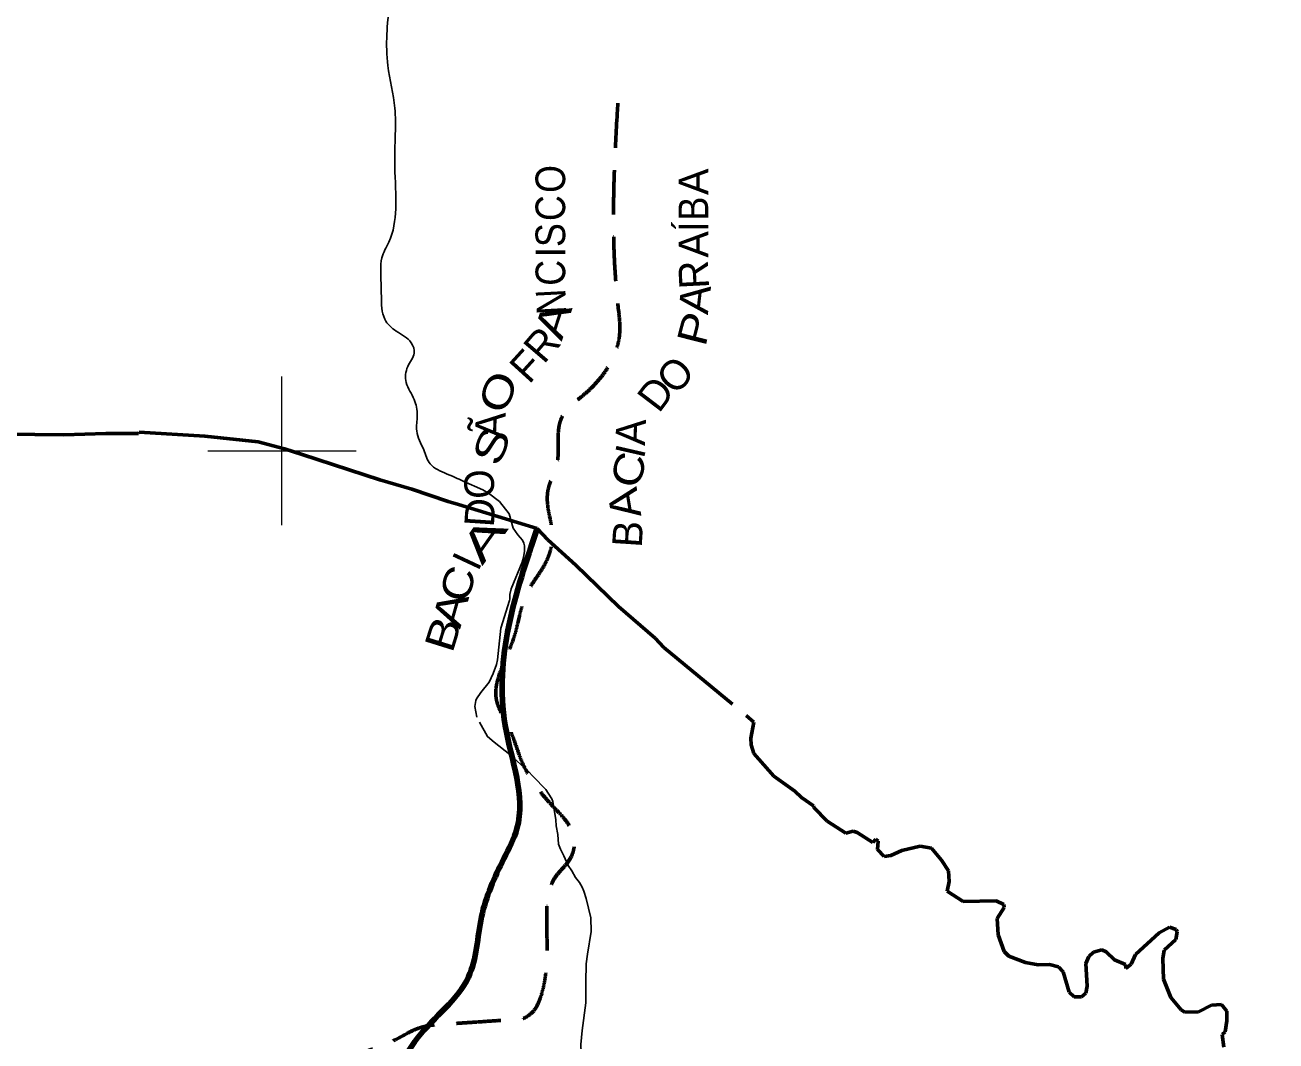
# Model space of a CAD drawing. Extents: x 553962 to 842807, y 8883888 to 9032388.
# Drawn here: x 746538 to 763398, y 8967044 to 8980740 of the extents above; entities that cross this region are included whole.
import ezdxf
from ezdxf.enums import TextEntityAlignment as Align

# ---------------------------------------------------------------- set-up
doc = ezdxf.new("R2010")
doc.units = 0
doc.header["$LTSCALE"] = 200
doc.linetypes.add('LONG_DASH_SHORT_DASH', pattern=[9.9, 6, -1.2, 1.5, -1.2])
doc.linetypes.add('MEDIUM_DASHED', pattern=[4.5, 3, -1.5])
for name, color, linetype, lineweight in [('10', 7, 'MEDIUM_DASHED', 60), ('12', 7, 'Continuous', 25), ('2', 7, 'Continuous', 13), ('24', 7, 'Continuous', 25), ('7', 7, 'LONG_DASH_SHORT_DASH', 60), ('9', 7, 'Continuous', 90)]:
    doc.layers.add(name, color=color, linetype=linetype, lineweight=lineweight)

msp = doc.modelspace()

# ---------------------------------------------------------------- linework, layer by layer
at = {"layer": '10'}
msp.add_spline([(753353.8, 8967411.3), (753402.1, 8967459.7), (753447.5, 8967537.9), (753569.9, 8968137.4), (753569.9, 8968618.2), (753685.3, 8969252.9), (753896.8, 8969522.2), (753935.3, 8969791.5), (753646.8, 8970214.6), (753242.9, 8970791.6), (753050.6, 8971291.7), (752896.7, 8971618.7), (753127.5, 8972484.2), (753300.6, 8973080.5), (753550.6, 8973484.4), (753646.8, 8973869.1), (753589.1, 8974215.3), (753589.1, 8974484.5), (753704.5, 8974811.5), (753723.7, 8975177), (753762.2, 8975427), (754089.2, 8975773.2), (754377.7, 8976100.2), (754550.8, 8976561.8), (754531.6, 8976946.5), (754538.8, 8979865.5)], degree=3, dxfattribs=at)
msp.add_open_spline([(751718.9, 8957290.2), (751531.6, 8957712.2), (750995.8, 8957861.4), (750836, 8958259.9), (750739.1, 8958501.4), (750810.6, 8958803), (750701.7, 8959043.4), (750649.5, 8959158.5), (750585.8, 8959273.1), (750522.6, 8959379.2), (750416.4, 8959557.6), (750245.2, 8959714.4), (750142.1, 8959894), (750059.8, 8960037.4), (750424.3, 8960195.8), (750388.3, 8960341.7), (750306, 8960675.5), (749757.2, 8960933.4), (749694.4, 8961281.9), (749657.1, 8961488.8), (749737.2, 8961760.6), (749694.4, 8961975.8), (749670.2, 8962097.1), (749510.2, 8962210.1), (749537.7, 8962334), (749613.3, 8962675.1), (749758.5, 8963019.6), (749851.1, 8963363.7), (749964, 8963783.7), (750022.5, 8964223.4), (750164.5, 8964639.7), (750243.4, 8964871.2), (750497.6, 8964991.5), (750634.5, 8965199.3), (750728.3, 8965341.6), (750833.7, 8965482.3), (750858.4, 8965647), (750892.9, 8965877.2), (750782, 8966109.4), (750768.8, 8966340.9), (750760.8, 8966481.8), (750668.1, 8966638.3), (750791.2, 8966766.2), (750923.4, 8966903.6), (751072.8, 8966882.1), (751216.6, 8966934), (751537.1, 8967049.7), (751840, 8967247.2), (752179.1, 8967269.8), (752291, 8967277.3), (752403, 8967284.8), (752514.9, 8967292.2), (752738.7, 8967307.2), (752962.6, 8967322.1), (753186.4, 8967337), (753247.3, 8967341.1), (753307.9, 8967370.8), (753353.8, 8967411.3)], degree=3, dxfattribs=at)
at = {"layer": '12'}
for points in [[(752444.7, 8974591.9), (752707.4, 8974475.5), (752786.5, 8974428), (752930.8, 8974317.1), (753062.6, 8974152.6), (753117.5, 8973959.1), (753180.2, 8973867.8), (753242.2, 8973795.8), (753262.4, 8973756.4), (753269, 8973717.7), (753270.2, 8973648.7), (753257.3, 8973562.4), (753237.5, 8973498.7), (753090.9, 8973141.2), (753070.7, 8973063.5), (753072.3, 8973000.7), (753069.1, 8972980.9), (752948.8, 8972607.6), (752907.8, 8972182.6), (752892.3, 8972118.5), (752847.2, 8971998.1), (752793, 8971880.4), (752680.5, 8971744), (752622, 8971655), (752613.9, 8971634.4), (752600.5, 8971552.9), (752626, 8971408.9)], [(752664, 8971340.7), (752771, 8971148.4), (752859.2, 8971072.4), (753072.2, 8970907.4), (753319.1, 8970681.2), (753384.5, 8970609.5), (753558.8, 8970434.3), (753589.6, 8970386.1)], [(753589.6, 8970386.1), (753640.4, 8970306.5), (753650.2, 8970274.2), (753691.1, 8970026.8), (753698.8, 8969944.5), (753719.3, 8969828.1), (753728.3, 8969699.4), (753756.5, 8969629.3), (753798.1, 8969540.9)], [(753798.1, 8969540.9), (753859.8, 8969409.4), (753909.1, 8969336.8), (753959.2, 8969249.6), (754012.5, 8969179), (754046.6, 8969117.8), (754069.8, 8969065.7), (754101.8, 8968966.1), (754161.6, 8968706.3), (754168.3, 8968520.8), (754116.9, 8968213), (754102.8, 8968082.3), (754094.2, 8967837.6), (754098.2, 8967608.9), (754095, 8967556.7), (754045.7, 8967185.6), (754028.2, 8966994.8), (754035.8, 8966766.1), (754034.7, 8966701.8), (754052, 8966621.5), (754053.6, 8966322.7), (754067.7, 8966231)]]:
    msp.add_lwpolyline(points, dxfattribs=at)
msp.add_spline([(752444.7, 8974591.9), (752220.7, 8974690.3), (751998.9, 8974824.7), (751911.5, 8975012.9), (751817.4, 8975268.3), (751824.1, 8975476.7), (751783.8, 8975691.7), (751676.2, 8975920.3), (751696.4, 8976135.3), (751783.8, 8976316.8), (751743.5, 8976458), (751541.8, 8976612.5), (751387.2, 8976773.8), (751340.2, 8977083), (751333.5, 8977432.5), (751346.9, 8977600.6), (751441, 8977812.6), (751535.1, 8978263.1), (751521.7, 8978828), (751528.4, 8979271.8), (751521.7, 8979621.5), (751427.6, 8980193.1), (751414.1, 8980616.7), (751461.2, 8981006.8), (751622.5, 8981450.6), (751723.3, 8981645.6), (752140.5, 8982419.4)], degree=3, dxfattribs=at)
at = {"layer": '2'}
for p, q in [((750000, 8974000), (750000, 8976000)), ((749000, 8975000), (751000, 8975000))]:
    msp.add_line(p, q, dxfattribs=at)
at = {"layer": '24'}
msp.add_spline([(771983.6, 8980431.6), (771458.1, 8980369.7), (771148.9, 8980648.1), (771087.1, 8980988.4), (770932.5, 8981297.7), (770808.9, 8981638), (770345.2, 8981761.8), (770005.1, 8981885.5), (769819.6, 8982071.1), (769634.1, 8981854.6), (769479.5, 8982009.2), (769015.8, 8982318.6), (768923.1, 8982689.8), (768706.7, 8982937.2), (768593.5, 8983157.4), (768713.2, 8983415.3), (768842, 8983516.6), (768842, 8983590.2), (768630.3, 8983700.8), (768289.8, 8983940.2), (768207, 8984262.5), (768022.9, 8984465.2), (767700.8, 8984557.2), (767590.3, 8984640.1), (767553.5, 8985036.1), (767599.5, 8985266.4), (767599.5, 8985422.9), (767461.5, 8985607.1), (767314.2, 8985634.8), (767268.2, 8985533.4), (767139.4, 8985496.6), (766918.5, 8985616.3), (766789.6, 8985818.9), (766559.5, 8985957.1), (766219, 8986297.8), (765850.9, 8986500.4), (765363.1, 8986924.1), (764801.7, 8987504.3), (764663.6, 8987624), (764378.3, 8988066), (764295.5, 8988259.4), (764221.8, 8988296.3), (764083.8, 8988204.2), (763982.5, 8988268.6), (763669.6, 8988664.7), (763586.8, 8988683.1), (763540.8, 8988848.8), (763605.2, 8988913.3), (763665, 8988922.5), (763720.2, 8989088.3), (763554.6, 8989254.1), (763480.9, 8989475.1), (763628.2, 8989677.7), (763977.9, 8989935.6), (764143.6, 8990101.3), (764125.2, 8990285.5), (763849.1, 8990377.6), (763793.9, 8990525), (763591.4, 8990617.1), (763480.9, 8990635.5), (763260.1, 8990525), (763094.4, 8990525), (762965.5, 8990635.5), (762818.3, 8990856.5), (762781.5, 8990930.2), (762652.6, 8990967), (762450.1, 8991169.6), (762082, 8991335.4), (761916.3, 8991464.3), (761750.7, 8991464.3), (761640.2, 8991261.7), (761456.2, 8991059.1), (761382.5, 8990967), (761290.5, 8990948.6), (761198.5, 8991059.1), (761143.2, 8991298.6), (760867.1, 8991464.3), (760738.3, 8991666.9), (760499, 8991795.9), (760351.7, 8992035.3), (760094, 8992495.8), (759854.7, 8992403.7), (759652.3, 8992256.3), (759394.6, 8992477.3), (758971.2, 8992643.1), (758731.9, 8992753.6), (758639.9, 8993048.3), (758566.2, 8993324.6), (758695.1, 8993508.8), (758916, 8993453.6), (758879.2, 8993619.3)], degree=3, dxfattribs=at)
at = {"layer": '7'}
msp.add_lwpolyline([(746278.3, 8975226), (747060.9, 8975214.3), (747626.8, 8975234.9), (748067.1, 8975233), (748078.4, 8975249.4), (748961.7, 8975196.1), (749681.4, 8975121.3), (750036, 8975026.7), (750271.4, 8974951.8), (751320.7, 8974608), (751750.1, 8974483.8), (752242.5, 8974318.8), (752380.7, 8974278), (753439.5, 8973954.2), (753583.6, 8973799.8), (753961.2, 8973460.6), (754538, 8972903.3), (755030, 8972474.8), (755147.7, 8972349.6), (756362.8, 8971344), (756320.3, 8971125.1), (756323.8, 8971036.6), (756361.2, 8970920.9), (756631.5, 8970616), (756915, 8970410.1), (757002.6, 8970325.1), (757165.2, 8970215.8), (757167.7, 8970190.1), (757348.9, 8970005.6), (757600.5, 8969846.9), (757701.3, 8969872.7), (757754.8, 8969855.7), (757962.9, 8969718.5), (758005.2, 8969765.2), (758038.1, 8969737.6), (758029.7, 8969624), (758115.6, 8969531.9), (758205.5, 8969542.5), (758357.8, 8969613.2), (758603.6, 8969671), (758755.3, 8969645.6), (758888.7, 8969481.4), (758982.7, 8969336.6), (758994.5, 8969195.7), (758967.2, 8969062.8), (759180.8, 8968923.9), (759628.7, 8968933.4), (759730, 8968884.3), (759736.6, 8968843), (759642.6, 8968697.4), (759656.2, 8968476.3), (759734.5, 8968249.9), (759797.4, 8968186.8), (760020.8, 8968100.7), (760193.3, 8968069.4), (760346.5, 8968073.3), (760468.7, 8968041.8), (760531.4, 8967975.3), (760612.4, 8967703.8), (760676.7, 8967637.3), (760778.2, 8967637.3), (760833.4, 8967688.2), (760853, 8967781.7), (760833.6, 8968087.2), (760876.7, 8968185), (760939.1, 8968243.5), (761053, 8968271), (761107.6, 8968247.7), (761221.6, 8968138.1), (761368.5, 8968077.3), (761376.6, 8968022.9), (761447, 8968077.5), (761506.1, 8968210.7), (761825.6, 8968499.9), (761961, 8968579.3), (762052.9, 8968547.4), (762065.9, 8968514.3), (762049.6, 8968410.7), (761891.1, 8968267.7), (761875.3, 8968158.2), (761883.2, 8967876.5), (761983, 8967632.3), (762120.3, 8967463.7), (762171.6, 8967432.4), (762355.5, 8967436.4), (762528.1, 8967526.2), (762662.3, 8967534.7), (762735.1, 8967446.8), (762735.2, 8967316.2), (762713.7, 8967168.6), (762672.7, 8967130.8), (762696.2, 8966959)], dxfattribs=at)
at = {"layer": '9'}
msp.add_spline([(750521.5, 8957798.6), (750290, 8958657.6), (749980, 8960173.9), (749746.6, 8961538.9), (749919.1, 8962982.1), (750673.6, 8964858.9), (751354.2, 8966153.2), (751832.9, 8967092.2), (752515.2, 8967905.8), (752689.9, 8968716.5), (752991.6, 8969502.6), (753167.8, 8969908.5), (753010.5, 8971299.2), (753439.5, 8973954.2)], degree=3, dxfattribs=at)

# ---------------------------------------------------------------- texts
at = {"layer": '10'}
for s, rotation, width, p in [('O', 90.036, 0.9, (753817.8, 8978665.2)), ('C', 90.036, 0.9, (753818, 8978272.4)), ('B', 90.036, 0.9, (755746.5, 8978265.8)), ('S', 90.036, 0.9, (753818.2, 8977908.6)), ('Í', 90.036, 0.85, (755746.7, 8978022)), ('C', 90.036, 0.9, (753818.6, 8977399.4)), ('A', 83.512, 1.1, (755762.6, 8977022)), ('N', 92.943, 0.9, (753827.9, 8977019.2)), ('A', 72.093, 1.35, (753844.7, 8976698.2)), ('P', 75.752, 1.2, (755758.5, 8976597.7)), ('O', 68.654, 1.3, (753100.6, 8975721.6)), ('S', 68.232, 1.35, (753011.4, 8974993.7)), ('C', 75.108, 1.2, (754866.1, 8974693.7)), ('O', 92.819, 0.95, (752858.4, 8974562.2)), ('A', 99.428, 1.15, (754812.1, 8974324.5)), ('A', 54.756, 1.75, (752879.4, 8973696.6)), ('C', 73.461, 1.2, (752562.8, 8973151.1)), ('A', 74.159, 1.3, (752463.3, 8972809.8)), ('B', 72.657, 1.25, (752362.1, 8972471.4))]:
    msp.add_text(s, height=400, rotation=rotation, dxfattribs=dict(at, width=width)).set_placement(p, align=Align.CENTER)
for s, rotation, p in [('A', 90.036, (755746.3, 8978627.4)), ('A', 90.036, (755746.8, 8977783.2)), ('I', 90.036, (753818.4, 8977676.6)), ('R', 92.943, (755748.6, 8977384.2)), ('R', 49.429, (753655.3, 8976304.3)), ('F', 47.713, (753441.2, 8976008.7)), ('O', 47.713, (755448.4, 8975892)), ('D', 52.701, (755198, 8975649.5)), ('Ã', 87.425, (753008, 8975336.6)), ('A', 87.425, (754900.6, 8975243.2)), ('I', 77.053, (754893.2, 8974952.8)), ('D', 86.239, (752868.5, 8974156.8)), ('B', 86.239, (754860, 8973866)), ('I', 64.893, (752674.8, 8973428.8))]:
    msp.add_text(s, height=400, rotation=rotation, dxfattribs=at).set_placement(p, align=Align.CENTER)

doc.saveas('drawing.dxf')
